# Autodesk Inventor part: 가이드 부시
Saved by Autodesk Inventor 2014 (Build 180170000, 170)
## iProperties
Created: 2026-06
Part Number: 가이드 부시
Material: 일반
Document SubType Name: Modeling
Designer: dg
Density: 1 g/cm^3
Appearance: 기본값
Author: dg
Author: jhkim
Creation Date: 2026-05-29
Sending System: Autodesk Inventor 2027
Preprocessor: ST-DEVELOPER v20.1
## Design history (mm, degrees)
node "가이드 부시1"
node "솔리드1"
node "기준1"
